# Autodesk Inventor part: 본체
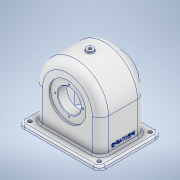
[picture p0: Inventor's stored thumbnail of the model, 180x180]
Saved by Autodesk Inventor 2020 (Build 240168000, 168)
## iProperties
Created: 2022-09
Part Number: 본체
Material: 알루미늄 6061
Document SubType Name: Modeling
Designer: com
Density: 2.7 g/cm^3
Appearance: 알루미늄 - 평지
Mass: 779.204 g
Surface Area: 1039.03 cm^2
Volume: 288.594 cm^3
Author: com
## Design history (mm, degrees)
sketch "스케치1"
  geometry: L1 (70, 54)-(-70, 54); L2 (-70, 54)-(-70, -54); L3 (-70, -54)-(70, -54); L4 (70, -54)-(70, 54); L5 (70, 54)-(-70, -54); L6 (-70, 54)-(70, -54); 1 further point
  constraints: 12 end point, 2 midpoint, 2 parallel, 1 horizontal, 1 perpendicular
  dimensions: "d0" = 140 distance of L3.end L2.end; "d1" = 108 distance of L2.end L1.end
extrude "돌출1" new body sketch "스케치1" distance "d2" = 7; taper "d3" = 0 deg
sketch "스케치3"
  geometry: L1 (-57, 39)-(57, 39); L2 (57, 39)-(57, -39); L3 (57, -39)-(-57, -39); L4 (-57, -39)-(-57, 39); L5 (-57, 39)-(57, -39); L6 (57, 39)-(-57, -39); 1 further point
  constraints: 12 end point, 2 midpoint, 2 parallel, 1 horizontal, 1 perpendicular
  dimensions: "d6" = 114 distance of L2.end L3.end; "d7" = 78 distance of L1.end L2.end
extrude "돌출2" join sketch "스케치3" distance "d8" = 114; taper "d9" = 0 deg
fillet "모깎기1" dims "d10" = 57
fillet "모깎기2" dims "d11" = 10
fillet "모깎기3" dims "d12" = 10
sketch "스케치7"
  geometry: C1 r 32 at (57, 57); A1 r 57 centre (57, 57) between (114, 57) and (0, 57) reference; 1 further point
  constraints: 1 centre point, 1 coincident
  dimensions: "d20" = 64 diameter of C1
extrude "돌출3" cut sketch "스케치7" distance "d22" = 3; taper "d23" = 0 deg
sketch "스케치12"
  geometry: A1 r 24 centre (0, 0) between (0, 24) and (-24, 0); 3 further points
  constraints: 4 point on circle, 1 centre point
  dimensions: "d40" = 48 diameter of A1
sketch "스케치13"
  geometry: L1 (-3, -7)-(117, -7) reference; C1 r 31 at (57, 57); 2 further points
  constraints: 1 centre point, 1 coincident
  dimensions: "d48" = 62 diameter of C1; "d102" = 64 distance from line of L1 C1.centre
extrude "돌출6" join sketch "스케치13" distance "d49" = 15; taper "d50" = 0 deg
sketch "스케치14"
  geometry: C1 r 20 at (0, 0); 1 further point
  constraints: 1 centre point
  dimensions: "d51" = 40 diameter of C1
extrude "돌출7" cut sketch "스케치14" distance "d52" = 16; taper "d53" = 0 deg
sketch "스케치15"
  geometry: C1 r 17.5 at (0, 0); 1 further point
  constraints: 1 centre point
  dimensions: "d54" = 35 diameter of C1
extrude "돌출8" cut sketch "스케치15" distance "d55" = 4; taper "d56" = 0 deg
sketch "스케치16"
  geometry: C1 r 1.23 at (0, -24) reference; C2 r 1.23 at (24, 0) reference; A1 r 24 centre (0, 0) between (0, 24) and (-24, 0); 4 further points
  constraints: 3 coincident, 2 point on circle, 1 centre point
  dimensions: "d57" = 48 diameter of A1
hole "구멍2" sketch "스케치16" at (0, 24), (-24, 0), (24, 0), (0, -24) diameter "d58" = 2.459; stored, may be unused: countersink angle "d62" = 90 deg, drill point angle "d64" = 118 deg; dims "d59" = 7, "d60" = 4, "d61" = 2, "d63" = 9
sketch "스케치17"
  geometry: L1 (-5, -7)-(83, -7) reference; L2 (0, 0)-(0, 57) reference; L3 (18.314, 13.1)-(59.793, 13.1); L4 (59.793, 13.1)-(59.793, 7.096); L5 (59.793, 7.096)-(18.314, 7.096); L6 (18.314, 7.096)-(18.314, 13.1); 2 further points
  constraints: 2 other
  dimensions: "d65" = 17 distance from line of L1 point (39, 10); "d66" = 39 distance from line of L2 point (39, 10)
feature "엠보싱1" sketch "스케치17" dims "d11" = 10, "d67" = 0.5, "d68" = 0
sketch "스케치18"
  geometry: C1 r 3.3 at (-60, -44); C2 r 3.3 at (60, -44); C3 r 3.3 at (-60, 44); C4 r 3.3 at (60, 44); A1 r 10 centre (-60, -44) between (-70, -44) and (-60, -54) reference; A2 r 10 centre (60, -44) between (60, -54) and (70, -44) reference; A3 r 10 centre (-60, 44) between (-60, 54) and (-70, 44) reference; A4 r 10 centre (60, 44) between (70, 44) and (60, 54) reference; 1 further point
  constraints: 4 centre point, 4 coincident
  dimensions: "d69" = 6.6 diameter of C1; "d70" = 6.6 diameter of C2; "d71" = 6.6 diameter of C3; "d72" = 6.6 diameter of C4
extrude "돌출9" cut sketch "스케치18" extent not by distance; stored distance "d73" = 0; taper "d74" = 0 deg
fillet "모깎기4" dims "d75" = 14
fillet "모깎기5" dims "d76" = 3
fillet "모깎기9" dims "d82" = 3
sketch "스케치19"
  geometry: 1 further point
node "작업 평면1"
sketch "스케치20"
  geometry: C1 r 6 at (0, 0); 1 further point
  constraints: 1 centre point, 1 coincident
  dimensions: "d84" = 12 diameter of C1
extrude "돌출10" join sketch "스케치20" stored distance "d85" = 5; taper "d86" = 0 deg
sketch "스케치21"
  geometry: 2 further points
  constraints: 1 coincident
hole "구멍3" sketch "스케치21" at (0, 0) diameter "d87" = 5.1881; stored, may be unused: countersink angle "d91" = 90 deg, drill point angle "d93" = 118 deg; dims "d88" = 12, "d89" = 4, "d90" = 2, "d92" = 16
fillet "모깎기10" dims "d94" = 1
fillet "모깎기11" dims "d95" = 0.6
chamfer "모따기1" distance "d96" = 1; stored, may be unused: second distance "d97" = 2, angle "d98" = 45 deg
sketch "스케치8"
  geometry: C1 r 20 at (0, 0); 1 further point
  constraints: 1 centre point
  dimensions: "d24" = 40 diameter of C1
extrude "돌출4" cut sketch "스케치8" distance "d25" = 16; taper "d26" = 0 deg
chamfer "모따기2" distance "d99" = 1; stored, may be unused: second distance "d100" = 2, angle "d101" = 45 deg
sketch "스케치10"
  geometry: L1 (60, 0)-(-60, 0) reference; L2 (52, 64)-(52, 0); L3 (52, 0)-(-50.377, 0); L4 (-52, 64)-(-52, 0); L5 (-52, 64)-(13, 64); A1 r 57 centre (0, 64) between (57, 64) and (-57, 64) reference; A2 r 52 centre (0, 64) between (52, 64) and (-52, 64); 4 further points
  constraints: 8 end point, 4 point on circle, 2 point on line, 2 vertical, 1 centre point, 1 coincident, 1 horizontal, 1 perpendicular, 1 tangent
  dimensions: "d32" = 104 diameter of A2; "d79" = 64 distance of L4.start L4.end; "d80" = 90 deg angle of L4 L5 (derived)
extrude "돌출5" cut sketch "스케치10" stored distance "d33" = 68; taper "d34" = 0 deg
sketch "스케치22"
  geometry: L1 (107, 34)-(64, 34) reference; L2 (100.083, 34)-(92, 20); L3 (92, 20)-(64, 20); L4 (65.23, 34)-(62.771, 34) reference; L5 (100.083, 34)-(64, 34); L6 (44, 35)-(84, 35) reference; L7 (0, 57.927)-(0, 0); L8 (64, 34)-(64, 20); 7 further points; 1 other entity
  constraints: 10 end point, 2 parallel, 2 point on line, 1 horizontal, 1 vertical, 2 other
  dimensions: "d106" = 60 deg angle of L3 L2; "d115" = 28 distance of L3.end L2.end; "d124" = 14 distance of L5.end L3.end
revolve "회전5" stored, may be unused: angle "d116" = 90 deg
sketch "스케치24"
  geometry: C1 r 20 at (0, 0); 3 further points; 1 other entity
  constraints: 1 centre point, 1 vertical alignment
  dimensions: "d109" = 40 diameter of C1
extrude "돌출11" cut sketch "스케치24" distance "d110" = 20; taper "d111" = 0 deg
hole "구멍4" sketch "스케치12" diameter "d117" = 2.459; stored, may be unused: countersink angle "d121" = 90 deg, drill point angle "d123" = 118 deg; dims "d118" = 7, "d119" = 4, "d120" = 2, "d122" = 9
fillet "모깎기14" dims "d125" = 3
fillet "모깎기15" dims "d126" = 9
node "솔리드1"
feature "A9D066F2-1C7D-4E18-AEED-F7BC21143FA4" dims "d58" = 2.459, "d59" = 7, "d60" = 4, "d61" = 2, "d62" = 90 deg, "d63" = 9, "d64" = 118 deg
other parameters: "d16" = 64, "d18" = 28, "d37" = 28, "d83" = 124, "d114" = 64
